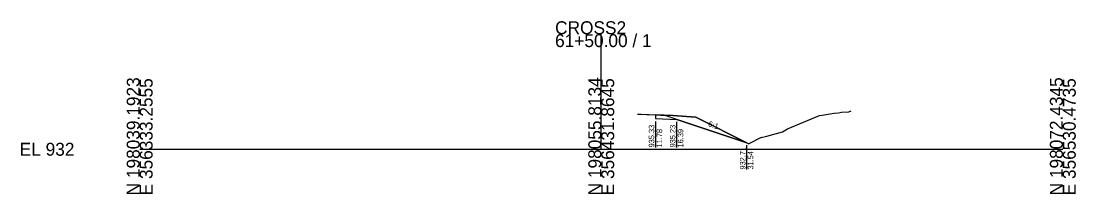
# Model space of a CAD drawing. Extents: x -26 to 203, y -10 to 14021.
# Drawn here: x -25.7 to 202.8, y 2490.3 to 2527.8 of the extents above; entities that cross this region are included whole.
import ezdxf

# ---------------------------------------------------------------- set-up
doc = ezdxf.new("R2010")
doc.units = 0
for name, color, linetype in [('Default', 7, 'Continuous'), ('P_E_XS_Ground', 7, 'Continuous'), ('P_XS', 7, 'Continuous'), ('P_XS_EAR_CommonGrnd', 7, 'Continuous'), ('P_XS_Lane', 7, 'Continuous'), ('P_XS_Rock', 7, 'Continuous')]:
    doc.layers.add(name, color=color, linetype=linetype)

msp = doc.modelspace()

# ---------------------------------------------------------------- linework, layer by layer
at = {"layer": 'Default'}
for p, q in [((100, 2500), (100, 2524.97)), ((0, 2500), (100, 2500)), ((100, 2500), (200, 2500))]:
    msp.add_line(p, q, dxfattribs=at)
at = {"layer": 'P_E_XS_Ground'}
for p, q in [((107.82, 2507.65), (108.31, 2507.62)), ((108.31, 2507.62), (108.63, 2507.61)), ((108.63, 2507.61), (115.5, 2507.34)), ((115.5, 2507.34), (120.5, 2506.94)), ((140.39, 2504.41), (147.31, 2507.32)), ((147.31, 2507.32), (147.85, 2507.43)), ((147.85, 2507.43), (150.48, 2507.82)), ((150.48, 2507.82), (151.41, 2507.93)), ((151.41, 2507.93), (152.05, 2508.08)), ((152.05, 2508.08), (153.64, 2508.14)), ((153.64, 2508.14), (154.13, 2508.32)), ((120.5, 2506.94), (131.98, 2501.2)), ((134.68, 2502.55), (131.98, 2501.2)), ((134.68, 2502.55), (135.86, 2502.87)), ((135.86, 2502.87), (139.27, 2503.8)), ((139.27, 2503.8), (140.39, 2504.41))]:
    msp.add_line(p, q, dxfattribs=at)
at = {"layer": 'P_XS'}
for p, q in [((107.82, 2507.65), (111.82, 2507.49)), ((111.82, 2507.49), (113.82, 2507.33)), ((116.39, 2506.47), (113.82, 2507.33))]:
    msp.add_line(p, q, dxfattribs=at)
at = {"layer": 'P_XS_EAR_CommonGrnd'}
msp.add_lwpolyline([(111.78, 2507.49), (111.78, 2506.65), (116.39, 2506.47), (131.54, 2501.42), (120.5, 2506.94), (115.5, 2507.34)], close=True, dxfattribs=at)
at = {"layer": 'P_XS_Lane'}
for p, q in [((111.78, 2507.49), (111.78, 2506.65)), ((111.78, 2506.65), (116.39, 2506.47)), ((131.54, 2501.42), (116.39, 2506.47))]:
    msp.add_line(p, q, dxfattribs=at)
at = {"layer": 'P_XS_Rock'}
for p, q in [((111.75, 2505.99), (111.75, 2500.39)), ((116.33, 2505.98), (116.33, 2500.39)), ((131.5, 2500.89), (131.5, 2495.6))]:
    msp.add_line(p, q, dxfattribs=at)

# ---------------------------------------------------------------- texts
at = {"layer": 'Default'}
for s, p in [('CROSS2', (90, 2524.97)), ('61+50.00 / 1', (90, 2522.17)), ('EL 932', (-26, 2498.6))]:
    msp.add_text(s, height=2.8, dxfattribs=at).set_placement(p)
for s, p in [('N 198039.1923', (0, 2490)), ('E 356333.2555', (2.8, 2490)), ('N 198055.8134', (100, 2490)), ('E 356431.8645', (102.8, 2490)), ('N 198072.4345', (200, 2490)), ('E 356530.4735', (202.8, 2490))]:
    msp.add_text(s, height=2.8, rotation=90, dxfattribs=at).set_placement(p)
at = {"layer": 'P_XS_Rock'}
for s, rotation, p in [('935.33', 90, (111.5, 2500.39)), ('935.23', 90, (116.08, 2500.39)), ('6:1', 341.5651, (123.07, 2505.02)), ('11.78', 90, (113.2, 2500.39)), ('16.39', 90, (117.78, 2500.39)), ('932.71', 90, (131.25, 2495.6)), ('31.54', 90, (132.95, 2495.6))]:
    msp.add_text(s, height=1.2, rotation=rotation, dxfattribs=at).set_placement(p)

doc.saveas('drawing.dxf')
